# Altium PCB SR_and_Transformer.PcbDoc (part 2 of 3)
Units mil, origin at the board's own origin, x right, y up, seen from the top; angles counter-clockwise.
Board outline 2362.61 x 1852.83 mil, 12 copper layers (Top Layer, Layer 1, Layer 2, Layer 3, Layer 4, Layer 5, Layer 6, Layer 7, Layer 8, Layer 9, Layer 10, Bottom Layer), stack 88.072 mil thick; 104 components, 44 nets, 388 pads, 1030 vias.
Unrouted connection lines stored in the file: 6.
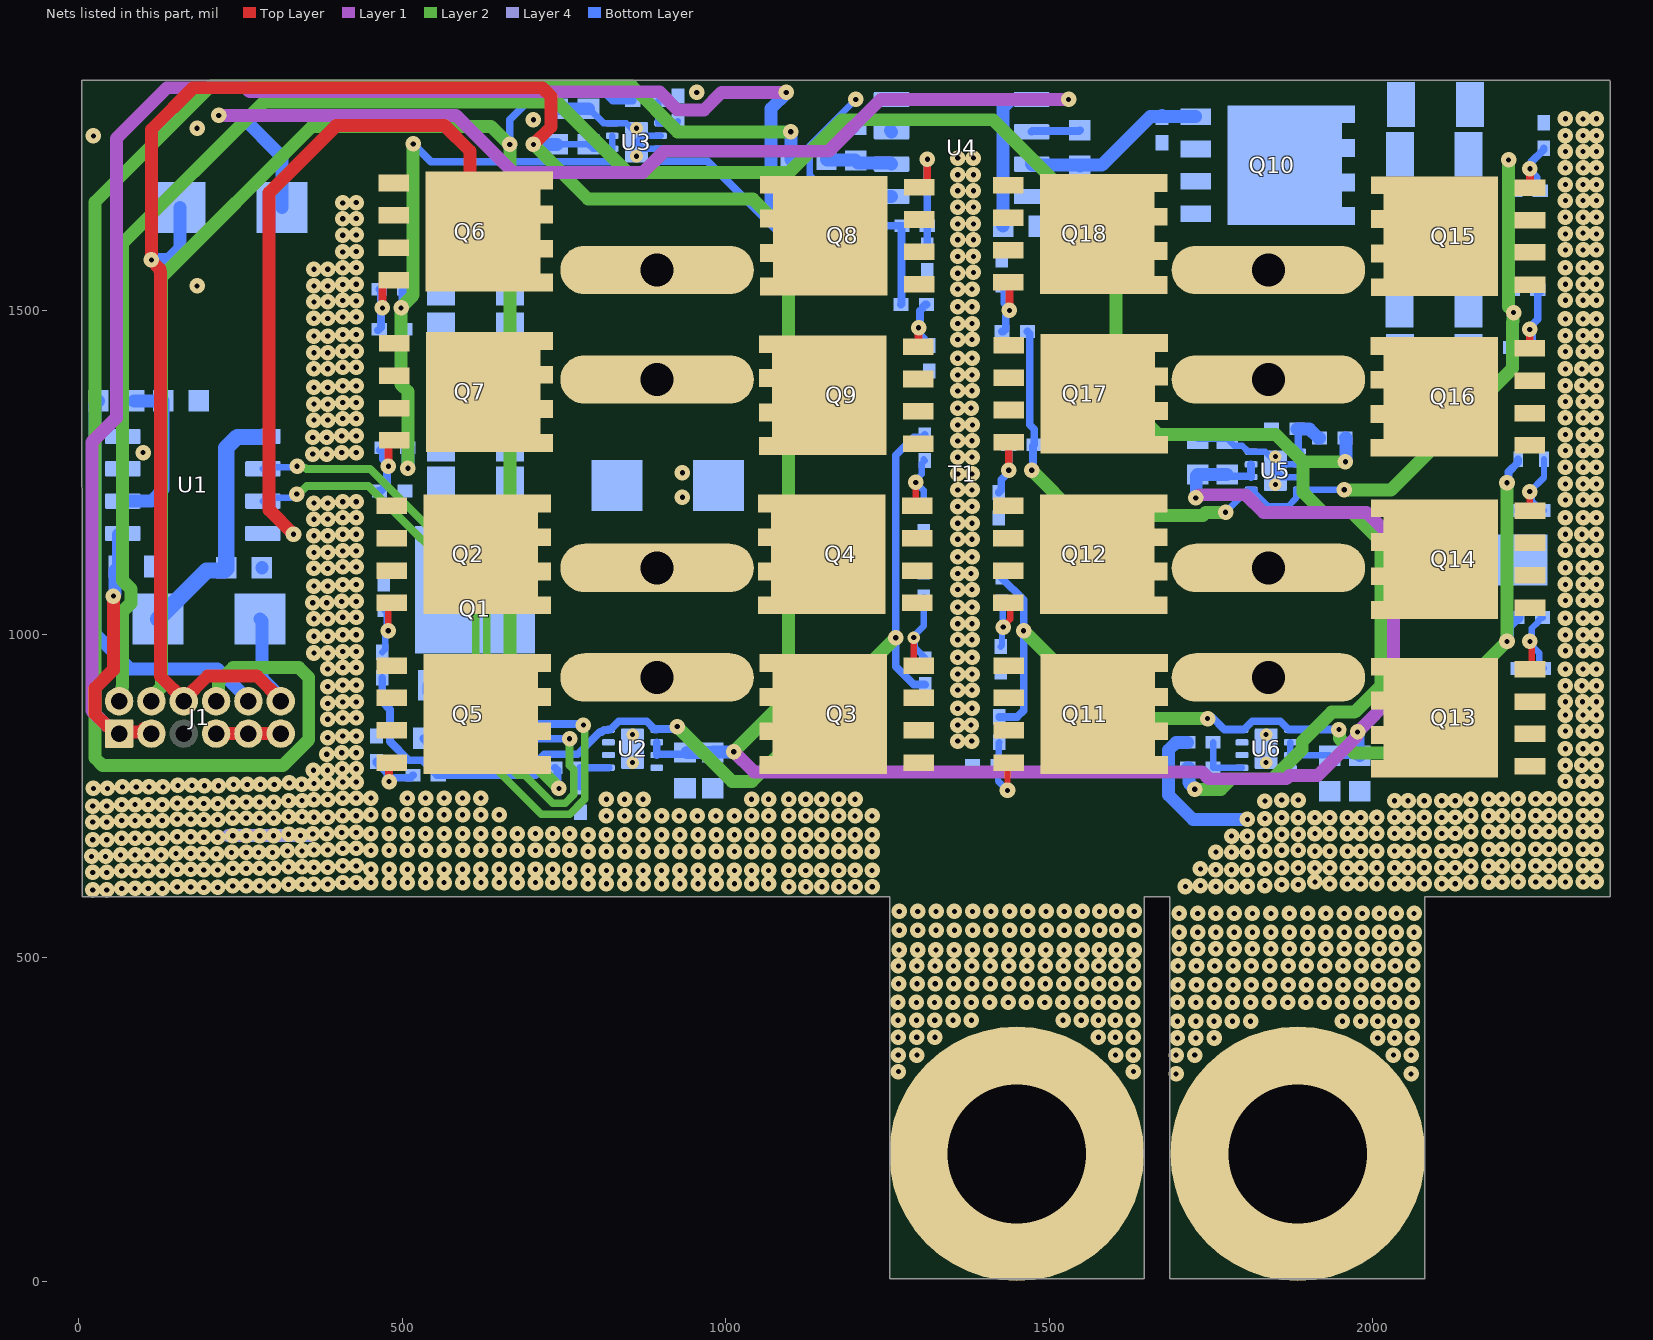
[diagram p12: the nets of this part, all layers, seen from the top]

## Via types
v1: diameter 24, hole 8, Top Layer to Bottom Layer, tented both sides, 1021 vias
v2: diameter 19.68, hole 7.87, Top Layer to Bottom Layer, 8 vias
v3: diameter 19.68, hole 7.87, Top Layer to Bottom Layer, tented both sides, 1 vias

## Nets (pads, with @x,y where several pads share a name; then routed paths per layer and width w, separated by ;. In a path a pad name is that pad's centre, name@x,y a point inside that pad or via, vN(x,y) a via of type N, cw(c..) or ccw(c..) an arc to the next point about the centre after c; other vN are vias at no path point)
5Vs: C2.1 C16.1 J1.1 J1.3 U1.1 U4.1 | length 2840.3
  Top Layer w20: v1(53.19,1059.24) 53.19,945.09 24.98,916.88 24.98,876.88 43.26,858.61 49.98,858.61 J1.1@62.03,846.56 ; J1.1@61.39,849.26 95.7,849.26 J1.3@100.66,854.22
  Layer 1 w20: J1.1@62.03,846.56 49.98,858.61 43.26,858.61 19.96,881.91 19.96,1296.95 57.81,1334.8 57.81,1766.69 136.13,1845 257.81,1845 264.03,1838.78 897.38,1838.78 925.46,1810.7 966.18,1810.7 993.18,1837.7 v1(1093.44,1837.7)
  Bottom Layer w20: v1(53.19,1059.24) 53.19,1060.32 55.63,1062.77 55.63,1099.13 C16.1@61.38,1104.88 61.38,1154.17 63.19,1155.98 U1.1@67.73,1155.98 ; v1(1093.44,1837.7) 1093.44,1836.62 1069.79,1812.97 1069.79,1667.94 1101.35,1636.38 C2.1@1204.86,1636.38 1205.84,1636.38 1238.7,1669.23 1238.7,1675.09 1240.51,1676.9 U4.1@1256.26,1676.9
12Vs: C10.1 C11.1 C13.1 C14.1 C24.1 C25.1 C27.1 C28.1 D2.2 D4.2 J1.6 J1.12 U2.6 U2.7 U3.6 U3.7 U5.6 U5.7 U6.6 U6.7 | length 5629.9
  Top Layer w20: J1.6@162.03,896.56 J1.6@162.03,898.95 ; J1.12@312.03,896.56 312.03,898.95 275.24,935.74 198.82,935.74 J1.6@162.03,898.95 ; v1@702.63,1757.49 729.63,1784.49 729.63,1831.68 716.31,1845 176.53,1845 112.03,1780.5 112.03,1577.8 125.14,1564.69 125.14,1560.88 126.15,1559.88 126.15,934.83 J1.6@162.03,898.95
  Layer 1 w20: v1(1012.42,818.52) 1043.51,787.43 1736.13,787.43 1746.83,776.74 1866.21,776.74 1871.37,781.89 1915.11,781.89 1975.98,842.76 1975.98,848.42 v1(1976.74,849.18) 2032.15,904.58 2032.15,1147.09 1990.76,1188.47 1831.23,1188.47 1803.88,1215.82 1732.58,1215.82 1727.58,1210.82 v1(1726.5,1210.82)
  Layer 2 w20: v1(702.63,1757.44) 787,1673.07 1041.73,1673.07 1097.26,1617.54 1097.26,903.36 v1(1012.42,818.52) ; v1@1975.98,848.42 v1(1976.74,849.18) v1@1976.74,850.26
  Bottom Layer w10: C14.1@738.94,1757.44 C13.1@787.7,1757.44 794.19,1750.95 U3.6@824.41,1750.95 U3.7@824.41,1770.64 ; U6.6@1872.82,833.08 U6.7@1872.82,813.39 1932.89,813.39 C27.1@1933.72,812.56 C28.1@1980,812.56
  Bottom Layer w12: U2.6@893.4,833.08 U2.7@893.4,813.39 894.47,814.47 937.03,814.47 C10.1@940,817.44 ; C24.1@1775.14,1247.1 1778,1244.24 1811.01,1244.24 U5.6@1812.09,1243.16 U5.7@1812.09,1262.85
  Bottom Layer w20: v1(112.03,1578.88) 112.8,1579.65 138.49,1579.65 156.22,1597.37 D2.2@156.22,1659.71 ; D4.2@279.95,1023.72 282.87,1020.8 282.87,932.23 312.03,903.08 J1.12@312.03,896.56 ; v1(702.63,1757.44) C14.1@738.94,1757.44 ; C10.1@940,817.44 C11.1@979.93,817.44 980.47,817.98 1011.88,817.98 v1(1012.42,818.52) ; v1(1726.5,1210.82) 1727.26,1211.59 1727.26,1244.83 C25.1@1729.53,1247.1 C24.1@1775.14,1247.1 ; v1(1976.74,849.18) 1977.51,848.42 1977.51,815.05 C28.1@1980,812.56
ACL_DRV_H1: R24.2 U4.6 | length 75.7
  Bottom Layer w12: U4.6@1472.79,1776.9 1474.07,1778.18 1546.16,1778.18 R24.2@1547.44,1779.46
ACL_DRV_H2: R2.2 U1.6 | length 1185.7
  Layer 2 w12: v1(337.17,1260) 339.46,1257.7 349.87,1257.7 351.9,1255.67 450.13,1255.67 630.39,1075.4 630.39,830.25 678.51,782.12 689.29,782.12 732.47,738.94 751.52,738.94 765,752.42 765,790.63 758.55,797.08 v1(758.55,838.53)
  Bottom Layer w10: U1.6@284.26,1255.98 286.27,1257.99 335.15,1257.99 v1(337.17,1260)
  Bottom Layer w12: R2.2@532.19,839.45 532.19,838.46 558.94,811.71 647.97,811.71 674.79,838.53 v1(758.55,838.53)
ACL_DRV_L1: Q10.4 R24.1 R25.1 U4.7 | length 288
  Bottom Layer w20: U4.7@1472.79,1726.9 1474.07,1725.62 1546.16,1725.62 R24.1@1547.44,1724.34 1548.39,1725.29 1581.14,1725.29 1656.17,1800.31 1674.12,1800.31 R25.1@1674.28,1800.47 ; R25.1@1674.28,1802.13 1674.28,1800.48 1674.44,1800.32 Q10.4@1726.5,1800.32
ACL_DRV_L2: Q1.4 R2.1 R3.1 U1.7 | length 1288.5
  Layer 2 w12: v1(336.62,1216.94) 339.86,1216.94 352.33,1229.4 447.53,1229.4 613.39,1063.53 613.39,823.2 714.65,721.94 758.57,721.94 782,745.38 782,857.57 v1(779.8,859.77)
  Bottom Layer w10: U1.7@284.26,1205.98 289.22,1210.93 326.82,1210.93 332.83,1216.94 v1(336.62,1216.94)
  Bottom Layer w12: Q1.4@537.31,921.45 537.31,910.62 577.56,870.37 577.56,849.19 R2.1@587.31,839.45 587.61,839.74 630.1,839.74 R3.1@630.39,840.04 649.65,840.04 671.14,861.53 778.04,861.53 v1(779.8,859.77)
NetC1_1: C1.1 R1.2 U1.2 | length 251.8
  Bottom Layer w20: U1.2@67.73,1205.98 67.78,1206.03 112.03,1206.03 130.25,1224.25 C1.1@130.25,1361.05 R1.2@85.37,1361.05
NetC3_1: C3.1 D4.1 U1.5 | length 387.9
  Bottom Layer w25: D4.1@122.47,1023.72 197.2,1098.45 224.51,1098.45 227.76,1101.7 C3.1@227.76,1102.69 227.76,1288.15 244.89,1305.29 283.58,1305.29 U1.5@284.26,1305.98
NetC4_1: C4.1 C5.1 C6.1 C7.1 C8.1 Q1.5 Q1.6 Q1.7 Q1.8 Q1.9 R4.2
NetC9_1: C9.1 R5.2 U2.1 | length 72.6
  Bottom Layer w12: C9.1@775.42,764.32 R5.2@775.42,793.71 U2.1@818.59,793.71
NetC12_1: C12.1 R16.2 U3.1 | length 66.4
  Bottom Layer w10: R16.2@895.42,1825 895.42,1790.4 895.49,1790.32 U3.1@899.22,1790.32 899.29,1790.4 923.64,1790.4 C12.1@926.11,1792.87
NetC15_1: C15.1 R23.2 U4.2 | length 103.7
  Bottom Layer w20: R23.2@1155.65,1734.41 1156.64,1733.42 1199.94,1733.42 C15.1@1200.92,1732.44 1204.65,1728.71 1254.45,1728.71 U4.2@1256.26,1726.9
NetC17_1: C17.1 D2.1 U4.5 | length 1890.4
  Layer 1 w20: v1(216.25,1802.28) 583.03,1802.28 671.01,1714.3 872.1,1714.3 904.68,1746.87 1159.08,1746.87 1239.1,1826.9 v1(1529.88,1826.9)
  Bottom Layer w20: v1(216.25,1802.28) 249.66,1802.28 313.7,1738.24 D2.1@313.7,1659.71 ; C17.1@1427.75,1631.9 C17.1@1428.7,1630.95 1428.7,1814.38 1441.22,1826.9 U4.5@1472.79,1826.9 v1(1529.88,1826.9)
NetC18_1: C18.1 C19.1 C20.1 C21.1 C22.1 Q10.5 Q10.6 Q10.7 Q10.8 Q10.9 R26.2
NetC23_1: C23.1 R30.2 U5.1 | length 77.8
  Bottom Layer w12: C23.1@1883.08,1317.77 1883.24,1317.61 1884.98,1315.86 1884.98,1283.61 1886.06,1282.53 U5.1@1886.89,1282.53
  Bottom Layer w20: C23.1@1883.24,1317.61 1902.13,1317.61 1916.23,1303.5 R30.2@1917.89,1303.5
NetC26_1: C26.1 R36.2 U6.1 | length 84.1
  Bottom Layer w10: C26.1@1753.33,833.08 R36.2@1753.33,793.71 U6.1@1798.01,793.71
NetQ2_4: Q2.4 R6.2 R10.2 | length 118.3
  Top Layer w10: v1(478.22,1005.51) 478.22,1043.3 Q2.4@483.53,1048.62
  Bottom Layer w10: R6.2@468.77,972.41 473.61,977.25 473.61,997.11 478.22,1001.72 v1(478.22,1005.51) 475.54,1008.18 475.54,1034.27 R10.2@471.23,1038.58
NetQ3_4: Q3.4 R7.2 R11.2 | length 162.4
  Top Layer w10: v3(1290.51,994.85) 1290.51,959.53 Q3.4@1298.31,951.74 Q3.4@1302.74,951.74
  Bottom Layer w10: R11.2@1306.62,1056.74 R11.2@1305.95,1057.41 1305.95,1012.9 1290.51,997.47 v3(1290.51,994.85) 1292.37,992.99 1292.37,979.14 1308.15,963.35 R7.2@1308.15,961.38 R7.2@1307.48,962.05
NetQ4_4: Q4.4 R8.2 R12.2 | length 124.1
  Top Layer w10: v1(1293.67,1234.85) 1293.67,1201.05 Q4.4@1296.1,1198.62
  Bottom Layer w10: v1(1293.67,1234.85) 1305.95,1222.52 R12.2@1305.95,1197.86 R12.2@1307.8,1199.71 ; v1(1293.67,1234.85) 1293.67,1238.64 1302.71,1247.68 1302.71,1263.78 R8.2@1307.55,1268.63 R8.2@1305.7,1270.48
NetQ5_4: Q5.4 R9.2 R13.2 | length 111
  Top Layer w12: v1(479.48,772.4) 479.48,797.69 Q5.4@483.53,801.74
  Bottom Layer w12: R13.2@460,803.55 460,801.58 477.19,784.39 477.19,774.7 v1(479.48,772.4) 482.73,772.4 488.61,778.28 512.43,778.28 R9.2@516.27,782.12
NetQ6_4: Q6.4 R14.2 R19.2 | length 132
  Top Layer w12: v1(469.08,1504.62) 469.3,1504.84 469.3,1540.94 476.09,1547.73 Q6.4@486.92,1547.73
  Bottom Layer w12: R19.2@462.51,1470.12 R19.2@464.18,1471.79 466.79,1474.4 466.79,1502.33 v1(469.08,1504.62) 466.79,1506.92 466.79,1531.04 R14.2@464.18,1533.65 ; v1@471.38,1510.17 471.38,1507.87 v1@474.63,1504.62
NetQ7_4: Q7.4 R15.2 R20.2 | length 134.4
  Top Layer w12: v1(478.47,1259.85) 478.47,1293 485.26,1299.8 Q7.4@487.17,1299.8 Q7.4@483.86,1296.49
  Bottom Layer w12: R20.2@462.59,1221.55 R20.2@464.56,1221.55 466.53,1221.55 470.37,1225.39 470.37,1227.36 476.17,1233.17 476.17,1257.56 v1(478.47,1259.85) 478.47,1262.27 469.92,1270.82 469.92,1287.33 R15.2@468.92,1288.32 R15.2@465.08,1284.48
NetQ8_4: Q8.4 R17.2 R21.2 | length 184.5
  Top Layer w12: Q8.4@1299.29,1691.3 1304.8,1691.3 1311.59,1698.09 v1(1311.59,1734.41)
  Bottom Layer w12: R21.2@1311.59,1601.34 R17.2@1311.59,1631.65 v1(1311.59,1734.41)
NetQ9_4: Q9.4 R18.2 R22.2 | length 107.5
  Top Layer w12: Q9.4@1297.71,1444.75 1298.05,1445.09 v1(1298.05,1474.08)
  Bottom Layer w12: R18.2@1310.2,1510 1308.23,1510 1304.39,1506.15 1304.39,1504.19 1300.34,1500.14 1300.34,1476.38 v1(1298.05,1474.08) 1300.34,1471.79 1300.34,1462.84 1314.57,1448.61 R22.2@1314.57,1446.65 ; R22.2@1310.73,1444.98 R22.2@1311.86,1446.11
NetQ11_4: Q11.4 R27.2 R32.2 | length 125.1
  Top Layer w10: v1(1435.5,758.63) 1435.5,799.88 Q11.4@1437.35,801.74
  Bottom Layer w10: R27.2@1422.59,833.03 1421.71,832.15 1421.71,798.26 R32.2@1420.82,797.38 1420.82,773.3 v1(1435.5,758.63)
NetQ12_4: Q12.4 R28.2 R33.2 | length 114.4
  Top Layer w10: v1(1428.91,1011.12) 1428.91,1012.49 1439.87,1023.45 1439.87,1045.33 Q12.4@1436.59,1048.62
  Bottom Layer w10: R33.2@1425.05,981.07 1426.98,983 1426.98,1009.2 v1(1428.91,1011.12) 1427.83,1012.21 1427.83,1048.51 R28.2@1426.75,1049.59
NetQ13_4: Q13.4 R29.2 R34.2 | length 142.9
  Top Layer w10: Q13.4@2243.21,946.04 2245.89,948.72 2245.89,986.47 v1(2243.21,989.15)
  Bottom Layer w10: R29.2@2262.6,1025.93 2260.64,1025.93 2255.79,1021.08 2255.79,1019.12 2245.89,1009.22 2245.89,991.83 v1(2243.21,989.15) 2243.21,985.36 2257.43,971.15 2257.43,952.22 2262.27,947.38 R34.2@2264.24,947.38
NetQ14_4: Q14.4 R31.2 R35.2 | length 128.9
  Top Layer w10: v1(2242.92,1220.63) 2242.92,1191.59 Q14.4@2243.21,1191.3
  Bottom Layer w10: R35.2@2264.72,1191.45 R35.2@2262.75,1191.45 2260.78,1191.45 2245.6,1206.63 2245.6,1217.95 v1(2242.92,1220.63) 2264.87,1242.58 R31.2@2264.87,1270.47
NetQ15_4: Q15.4 R37.2 R41.2 | length 111.6
  Top Layer w12: Q15.4@2243.21,1690.42 v1(2243.21,1719.75)
  Bottom Layer w12: R37.2@2259.23,1685.7 2257.26,1685.7 2253.42,1689.54 2253.42,1706.29 2243.21,1716.5 v1(2243.21,1719.75) 2245.51,1722.04 2245.51,1730.49 2264.41,1749.39 R41.2@2264.41,1751.36
NetQ16_4: Q16.4 R38.2 R42.2 | length 134.6
  Top Layer w12: Q16.4@2242.92,1442.08 v1(2242.92,1471.41)
  Bottom Layer w12: R38.2@2252.6,1443.4 2250.64,1443.4 2246.79,1447.25 2246.79,1464.29 2242.92,1468.16 v1(2242.92,1471.41) 2242.92,1474.66 2255.36,1487.1 R42.2@2255.36,1532.9 R42.2@2259.2,1529.05
NetQ17_4: Q17.4 R39.2 R43.2 | length 123.4
  Top Layer w12: v1(1437.36,1253.69) Q17.4@1437.36,1296.8
  Bottom Layer w12: R43.2@1421.82,1219.29 1425.67,1223.13 1425.67,1238.75 1437.36,1250.44 v1(1437.36,1253.69) R39.2@1437.35,1293.12
NetQ18_4: Q18.4 R40.2 R44.2 | length 126.4
  Top Layer w12: Q18.4@1436.59,1543.99 1438.43,1542.15 v1(1438.43,1500.88)
  Bottom Layer w12: R44.2@1426.75,1539.92 1430.59,1536.07 1430.59,1511.97 1438.43,1504.13 v1(1438.43,1500.88) 1438.43,1497.64 1432.71,1491.92 1432.71,1472.01 1428.87,1468.16 R40.2@1426.9,1468.16
PWM_ACL1: J1.8 R23.1 | length 2715.7
  Layer 2 w20: J1.8@212.03,896.56 215.85,900.38 215.85,926.35 238.26,948.76 339.92,948.76 355.28,933.39 355.28,837.18 315.18,797.08 36.7,797.08 24.98,808.79 24.98,1668.51 204.14,1847.67 854.88,1847.67 925.66,1776.9 v1(1100.54,1776.9)
  Bottom Layer w20: R23.1@1100.54,1734.41 v1(1100.54,1776.9)
PWM_ACL2: J1.10 R1.1 | length 644.1
  Bottom Layer w20: R1.1@30.25,1361.05 24.98,1355.78 24.98,1000.74 79.22,946.5 214.48,946.5 262.03,898.95 J1.10@262.03,896.56
SGND: C1.2 C2.2 C4.2 C5.2 C6.2 C7.2 C8.2 C9.2 C10.2 C11.2 C12.2 C13.2 C14.2 C15.2 C16.2 C18.2 C19.2 C20.2 C21.2 C22.2 C23.2 C24.2 C25.2 C26.2 C27.2 C28.2 D1.2 D3.2 J1.7 J1.9 J1.11 J3.1 Q2.1 Q2.2 Q2.3 Q3.1 Q3.2 Q3.3 Q4.1 Q4.2 Q4.3 Q5.1 Q5.2 Q5.3 Q6.1 Q6.2 Q6.3 Q7.1 Q7.2 Q7.3 Q8.1 Q8.2 Q8.3 Q9.1 Q9.2 Q9.3 Q11.1 Q11.2 Q11.3 Q12.1 Q12.2 Q12.3 Q13.1 Q13.2 Q13.3 Q14.1 Q14.2 Q14.3 Q15.1 Q15.2 Q15.3 Q16.1 Q16.2 Q16.3 Q17.1 Q17.2 Q17.3 Q18.1 Q18.2 Q18.3 R4.1 R10.1 R11.1 R12.1 R13.1 R19.1 R20.1 R21.1 R22.1 R26.1 R32.1 R33.1 R34.1 R35.1 R41.1 R42.1 R43.1 R44.1 U1.3 U1.4 U2.2 U2.3 U2.8 U2.9 U3.2 U3.3 U3.8 U3.9 U4.3 U4.4 U5.2 U5.3 U5.8 U5.9 U6.2 U6.3 U6.8 U6.9 | length 1160.7
  Top Layer w20: J1.7@212.03,846.56 J1.9@262.03,846.56 ; J1.9@262.3,846.56 J1.11@318.76,846.56
  Layer 4 w20: v1@230.87,689.03 v1@356.68,689.03
  Bottom Layer w10: C13.2@787.7,1812.56 788.68,1812.56 810.84,1790.4 819.57,1790.4 819.65,1790.32 U3.8@824.41,1790.32 824.49,1790.24 846.15,1790.24 853.94,1782.45 v2(861.81,1782.45) ; U3.3@899.22,1750.95 871.66,1750.95 U3.9@861.81,1760.79 871.66,1770.64 U3.2@899.22,1770.64 ; C15.2@1198.92,1789.56 C15.2@1200.92,1787.56 ; v1(1200.92,1826.9) 1129.91,1755.88 1129.91,1710.42 1148.83,1691.49 C2.2@1204.86,1691.49 ; C25.2@1729.53,1302.22 C24.2@1775.14,1302.22 1785.89,1291.47 1798.39,1291.47 1807.32,1282.53 U5.8@1812.09,1282.53 1812.17,1282.45 1833.82,1282.45 1849.49,1266.78 U5.9@1849.49,1253 ; U5.3@1886.89,1243.16 1859.33,1243.16 U5.9@1849.49,1253 ; U5.2@1886.89,1262.85 1859.33,1262.85 U5.9@1849.49,1253 ; R35.1@2223.38,1191.45 R35.1@2225.08,1193.14
  Bottom Layer w12: C2.2@1204.86,1691.49 C2.2@1205.84,1691.49
  Bottom Layer w20: C14.2@738.94,1812.56 C13.2@787.7,1812.56 ; U4.3@1254.45,1778.71 U4.3@1256.26,1776.9 ; C26.2@1713.96,833.08 1713.8,832.92 1696.26,832.92 1684.54,821.2 1684.54,751.5 1722.11,713.92 v1(1806.27,713.92)
  other v1: 1696.2,320.49 2059.48,320.49 1696.2,349.68 1724.95,349.68 2032.15,349.68 2059.48,349.68 1698.05,376 1726.79,376 1754.93,376 2007.77,376 2033.99,376 2061.33,376 1698.05,401.8 1726.79,401.8 1754.93,401.8 1783.25,401.8 1811.4,401.8 1953.24,401.8 1981.25,401.8 2007.77,401.8 2033.99,401.8 2061.33,401.8 1698.05,431 1726.79,431 1754.93,431 1783.25,431 1811.4,431 1839.89,431 1868.63,431 1896.77,431 1925.09,431 1953.24,431 1981.25,431 2007.77,431 2033.99,431 2061.33,431 1698.94,458.12 1727.68,458.12 1755.82,458.12 1784.14,458.12 1812.29,458.12 1840.78,458.12 1869.53,458.12 1897.67,458.12 1925.98,458.12 1954.13,458.12 1982.14,458.12 2008.66,458.12 2034.88,458.12 2062.22,458.12 1698.94,487.31 1727.68,487.31 1755.82,487.31 1784.14,487.31 1812.29,487.31 1840.78,487.31 1869.53,487.31 1897.67,487.31 1925.98,487.31 1954.13,487.31 1982.14,487.31 2008.66,487.31 2034.88,487.31 2062.22,487.31 1700.78,513.63 1729.53,513.63 1757.67,513.63 1785.99,513.63 1814.13,513.63 1842.63,513.63 1871.37,513.63 1899.51,513.63 1927.83,513.63 1955.98,513.63 1983.99,513.63 2010.5,513.63 2036.73,513.63 2064.07,513.63 1700.78,539.44 1729.53,539.44 1757.67,539.44 1785.99,539.44 1814.13,539.44 1842.63,539.44 1871.37,539.44 1899.51,539.44 1927.83,539.44 1955.98,539.44 1983.99,539.44 2010.5,539.44 2036.73,539.44 2064.07,539.44 1700.78,568.63 1729.53,568.63 1757.67,568.63 1785.99,568.63 1814.13,568.63 1842.63,568.63 1871.37,568.63 1899.51,568.63 1927.83,568.63 1955.98,568.63 1983.99,568.63 2010.5,568.63 2036.73,568.63 2064.07,568.63 21.4,604.99 42.97,604.99 66.13,607.25 86.91,607.25 107.26,607.29 128.84,607.29 193.03,608.86 214.61,608.86 152,609.55 172.78,609.55 1097.52,609.78 1123.74,609.78 1148.61,609.78 1174.84,609.78 1200.18,609.78 1226.4,609.78 1710.62,610.21 1757.67,610.21 1781.9,610.21 1806.27,610.21 237.77,611.12 258.55,611.12 279.39,611.16 300.96,611.16 1733.65,611.55 1833.45,611.55 324.13,613.42 344.9,613.42 1859.33,613.04 1884.92,613.04 363.16,613.89 384.74,613.89 787.1,614.36 815.42,614.36 843.57,614.36 872.07,614.36 900.81,614.36 928.95,614.36 957.27,614.36 985.42,614.36 1013.43,614.36 1039.94,614.36 1066.17,614.36 1933.72,614.21 1960.94,614.21 1981.72,614.21 2006.64,614.47 2033.86,614.47 2054.64,614.47 2079.72,614.44 2106.94,614.44 2127.72,614.44 407.9,616.15 428.68,616.15 451.35,616.15 479.48,616.15 507.8,616.15 535.95,616.15 564.45,616.15 593.19,616.15 621.33,616.15 649.65,616.15 677.8,616.15 705.81,616.15 732.32,616.15 758.55,616.15 1910.69,617.26 2152,617.03 2179.22,617.03 2200,617.03 2224.92,617.29 2252.14,617.29 2272.92,617.29 2298,617.26 2325.22,617.26 2346,617.26 21.4,632.02 42.97,632.02 66.13,634.28 86.91,634.28 107.26,634.31 128.84,634.31 787.1,635.1 815.42,635.1 843.57,635.1 872.07,635.1 900.81,635.1 928.95,635.1 957.27,635.1 985.42,635.1 1013.43,635.1 1039.94,635.1 1066.17,635.1 1097.26,635.1 1123.49,635.1 1148.35,635.1 1174.58,635.1 1199.92,635.1 1226.15,635.1 193.03,635.89 214.61,635.89 1757.67,636.07 1781.9,636.07 1806.27,636.07 152,636.57 172.78,636.57 451.35,636.89 479.48,636.89 507.8,636.89 535.95,636.89 564.45,636.89 593.19,636.89 621.33,636.89 649.65,636.89 677.8,636.89 705.81,636.89 732.32,636.89 758.55,636.89 1733.65,637.41 1833.45,637.41 237.77,638.14 258.55,638.14 279.39,638.19 300.96,638.19 1859.33,638.9 1884.92,638.9 1910.69,638.9 1933.72,638.9 1960.94,638.9 1981.72,638.9 2006.64,639.16 2033.86,639.16 2054.64,639.16 2079.72,639.13 2106.94,639.13 2127.72,639.13 324.13,640.45 344.9,640.45 363.16,639.75 384.74,639.75 407.9,642.01 428.68,642.01 2152,641.71 2179.22,641.71 2200,641.71 2224.92,641.98 2252.14,641.98 2272.92,641.98 2298,641.95 2325.22,641.95 2346,641.95 19.66,656.71 41.24,656.71 64.4,658.96 86.91,658.96 105.53,659 127.11,659 150.27,661.26 172.78,661.26 191.3,660.57 212.88,660.57 236.04,662.83 258.55,662.83 277.65,662.88 299.23,662.88 1757.67,663.38 1781.9,663.38 1806.27,663.38 787.1,664.3 815.42,664.3 843.57,664.3 872.07,664.3 900.81,664.3 928.95,664.3 957.27,664.3 985.42,664.3 1013.43,664.3 1039.94,664.3 1066.17,664.3 1097.26,664.3 1123.49,664.3 1148.35,664.3 1174.58,664.3 1199.92,664.3 1226.15,664.3 322.39,665.14 344.9,665.14 1833.45,664.72 1910.69,664.76 1933.72,664.76 1960.94,664.76 1981.72,664.76 2006.64,665.02 2033.86,665.02 2054.64,665.02 2079.72,664.99 2106.94,664.99 2127.72,664.99 451.35,666.09 479.48,666.09 507.8,666.09 535.95,666.09 564.45,666.09 593.19,666.09 621.33,666.09 649.65,666.09 677.8,666.09 705.81,666.09 732.32,666.09 758.55,666.09 1859.33,666.21 1884.92,666.21 363.16,666.78 384.74,666.78 2152,667.57 2179.22,667.57 2200,667.57 2224.92,667.83 2252.14,667.83 2272.92,667.83 2298,667.8 2325.22,667.8 2346,667.8 407.9,669.03 428.68,669.03 21.4,682.56 42.97,682.56 66.13,684.82 86.91,684.82 107.26,684.86 128.84,684.86 193.03,686.43 214.61,686.43 152,687.12 172.78,687.12 1781.9,688.07 1806.27,688.07 237.77,688.69 258.55,688.69 279.39,688.74 300.96,688.74 342.38,689.03 1833.45,689.41 787.1,690.1 815.42,690.1 843.57,690.1 872.07,690.1 900.81,690.1 928.95,690.1 957.27,690.1 985.42,690.1 1013.43,690.1 1039.94,690.1 1066.17,690.1 1097.26,690.1 1123.49,690.1 1148.35,690.1 1174.58,690.1 1199.92,690.1 1226.15,690.1 324.13,691 361.43,691.46 383.01,691.46 1859.33,690.9 1884.92,690.9 451.35,691.89 479.48,691.89 507.8,691.89 535.95,691.89 564.45,691.89 593.19,691.89 621.33,691.89 649.65,691.89 677.8,691.89 705.81,691.89 732.32,691.89 758.55,691.89 1910.69,692.07 1933.72,692.07 1960.94,692.07 1981.72,692.07 2006.64,692.33 2033.86,692.33 2054.64,692.33 2079.72,692.3 2106.94,692.3 2127.72,692.3 406.17,693.72 428.68,693.72 2152,694.88 2179.22,694.88 2200,694.88 2224.92,695.14 2252.14,695.14 2272.92,695.14 2298,695.11 2325.22,695.11 2346,695.11 21.4,709.88 42.97,709.88 66.13,712.13 86.91,712.13 107.26,712.17 128.84,712.17 152,714.43 172.78,714.43 193.03,713.74 214.61,713.74 1833.45,715.27 237.77,716 258.55,716 279.39,716.05 300.96,716.05 363.16,717.32 384.74,717.32 1859.33,716.76 1884.92,716.76 1910.69,716.76 1933.72,716.76 1960.94,716.76 1981.72,716.76 2006.64,717.02 2033.86,717.02 2054.64,717.02 2079.72,716.99 2106.94,716.99 2127.72,716.99 324.13,718.31 344.9,718.31 815.42,719.3 843.57,719.3 872.07,719.3 900.81,719.3 928.04,719.3 956.19,719.3 984.68,719.3 1013.43,719.3 1039.94,719.3 1066.17,719.3 1097.26,719.3 1123.49,719.3 1148.35,719.3 1174.58,719.3 1199.92,719.3 1226.15,719.3 407.9,719.58 428.68,719.58 2152,719.57 2179.22,719.57 2200,719.57 2224.92,719.83 2252.14,719.83 2272.92,719.83 2298,719.8 2325.22,719.8 2346,719.8 451.35,721.09 479.48,721.09 507.8,721.09 535.95,721.09 564.45,721.09 593.19,721.09 621.33,721.09 649.65,721.09 21.4,734.56 42.97,734.56 66.13,736.82 86.91,736.82 107.26,736.86 128.84,736.86 193.03,738.43 214.61,738.43 152,739.12 172.78,739.12 237.77,740.69 258.55,740.69 279.39,740.73 300.96,740.73 1833.45,742.3 324.13,742.99 344.9,742.99 2033.86,742.88 2054.64,742.88 2079.72,742.85 2106.94,742.85 2127.72,742.85 1859.33,743.78 1884.92,743.78 363.16,744.63 384.74,744.63 815.42,745.1 843.57,745.1 872.07,745.1 1039.94,745.1 1066.17,745.1 1097.26,745.1 1123.49,745.1 1148.35,745.1 1174.58,745.1 1199.92,745.1 2152,745.43 2179.22,745.43 2200,745.43 2224.92,745.69 2252.14,745.69 2272.92,745.69 2298,745.66 2325.22,745.66 2346,745.66 407.9,746.89 428.68,746.89 451.35,746.89 507.8,746.89 535.95,746.89 564.45,746.89 593.19,746.89 621.33,746.89 22.44,761.94 44.02,761.94 67.18,764.2 88.69,764.2 108.31,764.24 129.88,764.24 153.05,766.5 174.56,766.5 194.08,765.81 215.65,765.81 238.82,768.07 260.33,768.07 280.43,768.12 302.01,768.12 344.17,768.34 363.16,769.32 384.74,769.32 325.17,770.37 407.9,771.58 428.68,771.58 2298,772.69 2325.22,772.69 2346,772.69 362.43,789.88 384.01,789.88 407.17,792.14 428.68,792.14 2298,797.38 2323.49,797.38 2346,797.38 383.01,814.57 406.17,816.83 428.68,816.83 2298,823.23 2325.22,823.23 2346,823.23 1358.51,835.04 1380.12,835.08 384.74,840.43 407.9,842.68 428.68,842.68 2298,850.54 2325.22,850.54 2346,850.54 1358.51,859.73 1379.12,859.77 384.74,868.64 407.9,870.9 428.68,870.9 2298,875.23 2325.22,875.23 2346,875.23 1358.51,885.58 1380.85,885.63 384.74,893.33 407.9,895.59 428.68,895.59 2298,895.79 2324.49,895.79 2346,895.79 1358.51,913.8 1380.85,913.84 384.74,919.19 2298,920.48 2323.49,920.48 2346,920.48 407.9,921.45 428.68,921.45 1358.51,938.49 1380.85,938.53 384.74,946.5 2298,946.34 2325.22,946.34 2346,946.34 407.9,948.76 428.68,948.76 1358.51,964.35 1380.85,964.39 363.16,971.19 384.74,971.19 407.9,973.44 428.68,973.44 2298,974.55 2325.22,974.55 2346,974.55 1358.51,991.66 1380.85,991.7 363.16,997.04 384.74,997.04 407.9,999.3 428.68,999.3 2298,999.24 2325.22,999.24 2346,999.24 1358.51,1016.34 1380.85,1016.39 363.16,1024.07 384.74,1024.07 2298,1025.1 2325.22,1025.1 2346,1025.1 407.9,1026.33 428.68,1026.33 1358.51,1042.2 1380.85,1042.25 361.43,1048.76 383.01,1048.76 406.17,1051.02 428.68,1051.02 2298,1052.41 2325.22,1052.41 2346,1052.41 1358.51,1069.23 1380.85,1069.27 363.16,1074.62 384.74,1074.62 407.9,1076.88 428.68,1076.88 2298,1077.1 2325.22,1077.1 2346,1077.1 1358.51,1093.92 1379.12,1093.99 363.16,1101.93 384.74,1101.93 2298,1102.96 2325.22,1102.96 2346,1102.96 407.9,1104.19 428.68,1104.19 1358.51,1119.78 1380.85,1119.82 363.16,1126.62 384.74,1126.62 407.9,1128.87 428.68,1128.87 2298,1129.98 2325.22,1129.98 2346,1129.98 1358.51,1147.09 1380.85,1147.13 363.16,1152.47 384.74,1152.47 407.9,1154.73 428.68,1154.73 2298,1154.67 2323.49,1154.67 2346,1154.67 1358.51,1171.77 1380.85,1171.82 363.16,1178.02 384.74,1178.17 407.9,1180.43 428.68,1180.43 2298,1180.53 2325.22,1180.53 2346,1180.53 1358.51,1197.63 1380.85,1197.68 363.16,1202.86 384.74,1202.86 407.9,1205.12 428.68,1205.12 2298,1207.84 2325.22,1207.84 2346,1207.84 933,1211.83 1358.51,1223.33 1380.85,1223.38 2298,1232.53 2325.22,1232.53 2346,1232.53 1358.51,1248.02 1380.85,1248.06 933,1249.92 2298,1258.39 2325.22,1258.39 2346,1258.39 1358.51,1273.88 1380.85,1273.92 361.43,1278.67 383.01,1278.67 99.15,1280.92 406.17,1280.92 428.68,1280.92 2298,1284.09 2325.22,1284.09 2346,1284.09 1358.51,1299.14 1380.85,1299.18 361.43,1304.52 383.01,1304.52 406.17,1306.78 428.68,1306.78 2298,1308.77 2325.22,1308.77 2346,1308.77 1358.51,1323.82 1381.19,1323.82 363.16,1331.26 384.74,1331.26 407.9,1333.52 428.68,1333.52 2298,1334.63 2325.22,1334.63 2346,1334.63 1358.51,1349.68 1379.12,1349.73 363.16,1355.94 384.74,1355.94 407.9,1358.2 428.68,1358.2 2298,1359.89 2325.22,1359.89 2346,1359.89 1358.51,1376.41 1380.85,1376.46 363.16,1381.8 384.74,1381.8 407.9,1384.06 428.68,1384.06 2298,1384.58 2323.49,1384.58 2346,1384.58 1358.51,1401.1 1380.85,1401.15 2298,1410.44 2323.49,1410.44 2346,1410.44 363.16,1410.64 384.74,1410.64 407.9,1412.89 428.68,1412.89 1358.51,1426.96 1380.85,1427.01 363.16,1435.32 384.74,1435.32 2298,1437.17 2325.22,1437.17 2346,1437.17 407.9,1437.58 428.68,1437.58 1358.51,1455.79 1380.85,1455.84 363.16,1461.18 384.74,1461.18 2298,1461.86 2325.22,1461.86 2346,1461.86 407.9,1463.44 428.68,1463.44 1358.51,1480.48 1380.85,1480.52 363.16,1488.49 384.74,1488.49 2298,1487.72 2325.22,1487.72 2346,1487.72 407.9,1490.75 428.68,1490.75 1358.51,1506.34 1380.85,1506.38 363.16,1514.01 384.74,1514.01 428.68,1515.44 407.9,1516.27 2298,1516.55 2325.22,1516.55 2346,1516.55 1358.51,1533.65 1380.85,1533.69 182.56,1538.6 363.16,1538.6 384.74,1538.6 407.9,1540.86 428.68,1541.3 2298,1541.24 2325.22,1541.24 2346,1541.24 1358.51,1558.34 1382.82,1559.6 363.16,1564.3 384.74,1564.3 407.9,1566.56 428.68,1566.99 2298,1567.09 2325.22,1567.09 2346,1567.09 1358.51,1584.19 1382.82,1584.19 407.9,1591.25 428.68,1591.68 2298,1594.4 2325.22,1594.4 2346,1594.4 1358.51,1609.89 1382.82,1609.89 407.9,1617.1 428.68,1617.54 2298,1619.09 2346,1619.09 2325.22,1620.26 1358.51,1634.58 1382.82,1634.58 407.9,1642.36 428.68,1642.8 2298,1644.95 2325.22,1644.85 2346,1644.95 1358.51,1660.44 1382.82,1660.44 407.9,1667.05 428.68,1667.49 2298,1670.65 2325.22,1670.55 2346,1670.65 1358.51,1685.7 1382.82,1685.7 2298,1695.34 2325.22,1695.24 2346,1695.34 1358.51,1710.39 1382.82,1710.39 2298,1721.19 2325.22,1721.1 2346,1721.19 1358.51,1736.24 1382.82,1736.24 2298,1746.45 2325.22,1746.36 2346,1746.45 22.44,1770.64 2298,1771.14 2325.22,1771.05 2346,1771.14 182.56,1782.45 702.63,1795.67 2298,1797 2325.22,1796.9 2346,1797 955,1837.7
  other v2: 855.99,801.58 1835.42,801.58 855.99,844.89 1835.42,844.89 1849.49,1231.35 1849.49,1274.66 861.81,1739.14
SR1: J1.2 R30.1 R36.1 | length 3994.6
  Layer 2 w20: J1.2@62.03,896.56 66.64,901.17 66.64,918.21 67.18,918.74 67.18,1035.05 80.19,1048.06 80.19,1070.43 67.18,1083.43 67.18,1604.1 285.75,1822.67 739.48,1822.67 847.86,1714.3 1098.29,1714.3 1179.54,1795.55 1412.93,1795.55 1602.97,1605.5 1602.97,1374.76 1668.62,1309.11 1850.17,1309.11 1892.5,1266.78 ; v1(1724.95,760.43) 1765.54,760.43 1781.84,776.74 1845.71,776.74 1891.16,822.19 1891.16,834.31 1936.61,879.76 1972.18,879.76 2012.9,920.48 2012.9,1143.23 1967.65,1188.47 1923.46,1188.47 1892.5,1219.43 1892.5,1266.78 ; v1(1957.95,1266.78) 1892.5,1266.78
  Bottom Layer w20: R36.1@1713.96,793.71 1715.61,793.71 1715.77,793.55 1715.77,770.69 1724.95,761.52 v1(1724.95,760.43) ; R30.1@1957.79,1303.5 1958.55,1303.5 1958.71,1303.35 1958.71,1267.55 v1(1957.95,1266.78)
SR2: J1.4 R5.1 R16.1 | length 2626.7
  Layer 2 w20: J1.4@112.03,896.56 112.03,903.08 127.32,918.36 127.32,1552.06 360.44,1785.19 637.22,1785.19 664.97,1757.44 v1(666.05,1757.44) 666.05,837.89 v1(742,761.94)
  Bottom Layer w12: v1(666.05,1757.44) 666.05,1795.67 715.38,1845 805.12,1845 825.12,1825 R16.1@856.05,1825 ; R5.1@736.05,793.71 739.7,790.06 739.7,764.24 v1(742,761.94)
T1: C17.2 D3.1 Q10.1 Q10.2 Q10.3 Q11.5 Q11.6 Q11.7 Q11.8 Q11.9 Q12.5 Q12.6 Q12.7 Q12.8 Q12.9 Q13.5 Q13.6 Q13.7 Q13.8 Q13.9 Q14.5 Q14.6 Q14.7 Q14.8 Q14.9 Q15.5 Q15.6 Q15.7 Q15.8 Q15.9 Q16.5 Q16.6 Q16.7 Q16.8 Q16.9 Q17.5 Q17.6 Q17.7 Q17.8 Q17.9 Q18.5 Q18.6 Q18.7 Q18.8 Q18.9 R25.2 T1.7 T1.9 U4.8 | length 231.1
  Bottom Layer w50: T1.7@1726.5,1563.32 T1.7@1838.7,1563.32 T1.7@1957.62,1563.32
T2: C3.2 D1.1 Q1.1 Q1.2 Q1.3 Q2.5 Q2.6 Q2.7 Q2.8 Q2.9 Q3.5 Q3.6 Q3.7 Q3.8 Q3.9 Q4.5 Q4.6 Q4.7 Q4.8 Q4.9 Q5.5 Q5.6 Q5.7 Q5.8 Q5.9 Q6.5 Q6.6 Q6.7 Q6.8 Q6.9 Q7.5 Q7.6 Q7.7 Q7.8 Q7.9 Q8.5 Q8.6 Q8.7 Q8.8 Q8.9 Q9.5 Q9.6 Q9.7 Q9.8 Q9.9 R3.2 T1.3 T1.5 U1.8 | length 1166.1
  Top Layer w20: v1(331.71,1154.73) 294.03,1192.41 294.03,1682.77 397.67,1786.41 565.4,1786.41 604.5,1747.32 604.5,1642.95 Q6.9@624.72,1622.73
  Bottom Layer w20: C3.2@282.87,1102.69 C3.2@282.87,1103.67
  Bottom Layer w50: T1.3@774.9,933.39 T1.3@893.82,933.39
Vg1: R37.1 R38.1 R39.1 R40.1 U5.4 U5.5 | length 1543.8
  Layer 2 w20: v1(1472.89,1253.69) 1542.75,1183.82 1737.68,1183.82 1741.91,1188.06 1771.91,1188.06 v1(1772.67,1188.82) ; v1(1955.99,1223.48) 2028.61,1223.48 2215.92,1410.78 2215.92,1482.59 2217.13,1483.8 2217.13,1496.54 v1(2217.89,1497.31) ; v1@2210.1,1506.18 v1(2210.1,1733.53)
  Bottom Layer w10: v1(1772.67,1188.82) 1807.32,1223.48 U5.5@1812.09,1223.48 1816.85,1223.48 1816.93,1223.4 1816.93,1219.28 1838.09,1198.12 1869.35,1198.12 1882.05,1210.82 1882.05,1223.4 1882.13,1223.48 U5.4@1886.89,1223.48 v1(1955.99,1223.48) ; v1(2210.1,1733.53) 2210.1,1695.46 2213.05,1692.51 2213.05,1690.54 2217.89,1685.7 R37.1@2219.86,1685.7 ; R38.1@2211.27,1443.4 R38.1@2213.23,1443.4 2215.2,1443.4 2215.56,1443.76 2215.56,1494.98 v1(2217.89,1497.31)
  Bottom Layer w12: R40.1@1466.27,1468.16 1469.83,1464.61 1469.83,1323.9 1476.72,1317 R39.1@1476.72,1293.12 1474.81,1291.21 1474.81,1255.61 v1(1472.89,1253.69)
Vg2: R14.1 R15.1 R17.1 R18.1 U3.4 U3.5 | length 1539.6
  Layer 2 w20: v1(508.6,1256.69) 508.6,1375.39 498.08,1385.92 v1(498.08,1504.62) 498.08,1505.71 516.73,1524.36 v1(516.73,1758.19)
  Bottom Layer w12: v1(498.08,1504.62) 500.38,1506.92 500.38,1530.48 R14.1@503.55,1533.65 ; v1(516.73,1758.19) 544.23,1730.69 823.84,1730.69 U3.5@824.41,1731.27 827.18,1731.27 840.15,1718.3 883.48,1718.3 896.45,1731.27 U3.4@899.22,1731.27 971.8,1731.27 1093.44,1609.63 1226.15,1609.63 1232.59,1616.07 1232.59,1621.83 1242.41,1631.65 R17.1@1272.22,1631.65 1271.53,1630.95 1271.53,1510.7 R18.1@1270.83,1510
  Bottom Layer w20: R15.1@508.29,1288.32 508.45,1288.17 508.45,1256.84 v1(508.6,1256.69)
Vg3: R27.1 R28.1 R29.1 R31.1 U6.4 U6.5 | length 1502.1
  Layer 2 w20: v1(1460.45,1005.51) 1596.23,869.73 v1(1744.92,869.73) ; v1(1947.8,852.76) 1948.56,852 1948.56,839.18 1971.32,816.42 2034.95,816.42 2099.53,880.99 v1(2207.68,989.15) v1(2207.68,1234.41)
  Bottom Layer w12: R27.1@1422.59,872.41 1450.56,872.41 1460.45,882.3 v1(1460.45,1005.51) ; R28.1@1426.75,1088.96 1426.75,1086.99 1460.45,1053.28 v1@1460.45,1008.75 ; v1@1751.21,872.41 1770.86,852.76 U6.4@1798.01,852.76 1800.78,852.76 1813.75,865.73 1857.08,865.73 1870.05,852.76 U6.5@1872.82,852.76 v1(1947.8,852.76) ; v1(2207.68,1234.41) 2209.98,1236.71 2209.98,1251.08 2224.87,1265.97 R31.1@2224.87,1270.47
  Bottom Layer w20: v1(2207.68,989.15) 2208.45,989.91 2208.45,1012.79 2221.58,1025.93 R29.1@2223.23,1025.93
Vg4: R6.1 R7.1 R8.1 R9.1 U2.4 U2.5 | length 1528.9
  Layer 2 w20: v1(924.93,857.38) 1009.9,772.4 1040.34,772.4 v1(1262.78,994.85)
  Bottom Layer w12: R6.1@468.77,933.04 468.77,895.95 480.84,883.88 480.84,834.37 509.92,805.29 530.51,805.29 553.67,782.12 R9.1@555.64,782.12 706.21,782.12 713.24,789.15 713.24,808.1 719.69,814.55 770.9,814.55 805.35,849 808.18,849 810.86,851.68 817.51,851.68 U2.4@818.59,852.76 821.36,852.76 834.32,865.73 877.66,865.73 890.63,852.76 U2.5@893.4,852.76 894.47,853.84 918.14,853.84 921.68,857.38 v1(924.93,857.38) ; R8.1@1307.55,1308 1304.08,1304.52 1290.51,1304.52 1262.78,1276.79 v1(1262.78,994.85) 1262.78,950.28 1290.51,922.54 1307.62,922.54 R7.1@1308.15,922.01
VSR: J2.1 T1.4 T1.6 T1.8 T1.10
  other v1: 1266.84,324 1630.13,324 1266.59,349.47 1295.34,349.47 1602.54,349.47 1629.88,349.47 1266.33,377.05 1295.08,377.05 1323.22,377.05 1576.05,377.05 1602.28,377.05 1629.62,377.05 1266.26,403.43 1295,403.43 1323.14,403.43 1351.46,403.43 1379.61,403.43 1521.45,403.43 1549.46,403.43 1575.98,403.43 1602.2,403.43 1629.54,403.43 1266,431 1294.74,431 1322.88,431 1351.2,431 1379.35,431 1407.84,431 1436.59,431 1464.73,431 1493.05,431 1521.19,431 1549.21,431 1575.72,431 1601.94,431 1629.28,431 1267.02,459.74 1295.77,459.74 1323.91,459.74 1352.23,459.74 1380.38,459.74 1408.87,459.74 1437.61,459.74 1465.75,459.74 1494.07,459.74 1522.22,459.74 1550.23,459.74 1576.74,459.74 1602.97,459.74 1630.31,459.74 1266.77,487.31 1295.51,487.31 1323.65,487.31 1351.97,487.31 1380.12,487.31 1408.61,487.31 1437.35,487.31 1465.49,487.31 1493.81,487.31 1521.96,487.31 1549.97,487.31 1576.49,487.31 1602.71,487.31 1630.05,487.31 1267.84,512.03 1296.59,512.03 1324.73,512.03 1353.05,512.03 1381.19,512.03 1409.69,512.03 1438.43,512.03 1466.57,512.03 1494.89,512.03 1523.04,512.03 1551.05,512.03 1577.56,512.03 1603.79,512.03 1631.13,512.03 1268.1,542.46 1296.85,542.46 1324.98,542.46 1353.3,542.46 1381.45,542.46 1409.95,542.46 1438.69,542.46 1466.83,542.46 1495.15,542.46 1523.3,542.46 1551.31,542.46 1577.82,542.46 1604.05,542.46 1631.39,542.46 1268.1,571.65 1296.85,571.65 1324.98,571.65 1353.3,571.65 1381.45,571.65 1409.95,571.65 1438.69,571.65 1466.83,571.65 1495.15,571.65 1523.3,571.65 1551.31,571.65 1577.82,571.65 1604.05,571.65 1631.39,571.65
pads on no net: J1.5

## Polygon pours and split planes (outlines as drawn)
VSR on Layer 8 "LAYER_8_VSR_P122" (solid, remove dead copper, pour order 122): 731.09,1673.07 731.09,857.34 1124.35,857.38 1255.17,726.55 1255.17,4.05 1649.92,4.05 1649.92,592.34 1681.79,592.34 2000.54,911.1 2000.54,1412.86 1964.9,1448.5 1413.91,1448.5 1413.91,827.02 1384.26,797.38 1380.06,801.58 1354.61,801.58 1327.8,828.4 1338.13,838.73 1338.13,1612.26 1272.87,1677.52
VSR on Layer 8 "LAYER_8_VSR_P078" (solid, remove dead copper, pour order 78): 1252.36,593.23 1253.73,594.6 1647.11,594.6 1647.11,4.05 1252.36,4.05
SGND on Layer 8 "LAYER_8_SGND_P126" (solid, remove dead copper, pour order 126): 4.92,1856.41 4.92,594.6 6.8,592.72 1686.92,592.72 1686.92,4.05 2081.55,4.05 2081.55,593.23 2082.92,594.6 2366.92,594.6 2366.92,1856.87
SGND on Top Layer "TOP_LAYER_SGND_P075" (solid, remove dead copper, pour order 75): 4.92,1856.87 4.92,597.03 2359.92,597.03 2362.35,594.6 2366,598.24 2366,1856.87
T1 on Top Layer "TOP_LAYER_T1_P073" (solid, remove dead copper, pour order 73): 1465.99,1742.48 1464.73,1741.21 1464.73,758.63 1697.56,758.63 1698.94,760 1695.05,763.89 1695.05,972.85 1988.91,972.85 1988.91,750.55 2201.17,750.55 2203.55,752.93 2200,756.48 2200,1733.53
T2 on Top Layer "TOP_LAYER_T2_P070" (solid, remove dead copper, pour order 70): 520,771.58 521.14,770.44 1258.79,770.44 1258.79,1731.27 1261.93,1734.41 1041.84,1734.41 1041.84,1521.2 745.64,1521.2 745.64,1735.99 740.79,1740.84 520,1740.84
VSR on Top Layer "TOP_LAYER_VSR_P050" (solid, remove dead copper, pour order 50): 1252.36,593.23 1643.24,593.23 1644.74,594.72 1647.11,592.35 1647.11,4.05 1252.36,4.05
SGND on Top Layer "TOP_LAYER_SGND_P046" (solid, remove dead copper, pour order 46): 1678.92,623.19 1678.92,602.16 1686.92,594.15 1686.92,4.05 2078.81,4.05 2078.81,623.19
VSR on Layer 9 "LAYER_9_VSR_P129" (solid, remove dead copper, pour order 129): 1255.17,593.23 1256.54,594.6 1649.92,594.6 1649.92,4.05 1255.17,4.05
SGND on Layer 9 "LAYER_9_SGND_P116" (solid, remove dead copper, pour order 116): 5.86,1857.8 5.86,593.66 1684.54,593.66 1686.92,591.28 1686.92,4.05 2080.18,4.05 2080.18,594.38 2366.92,594.38 2366.92,1856.87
